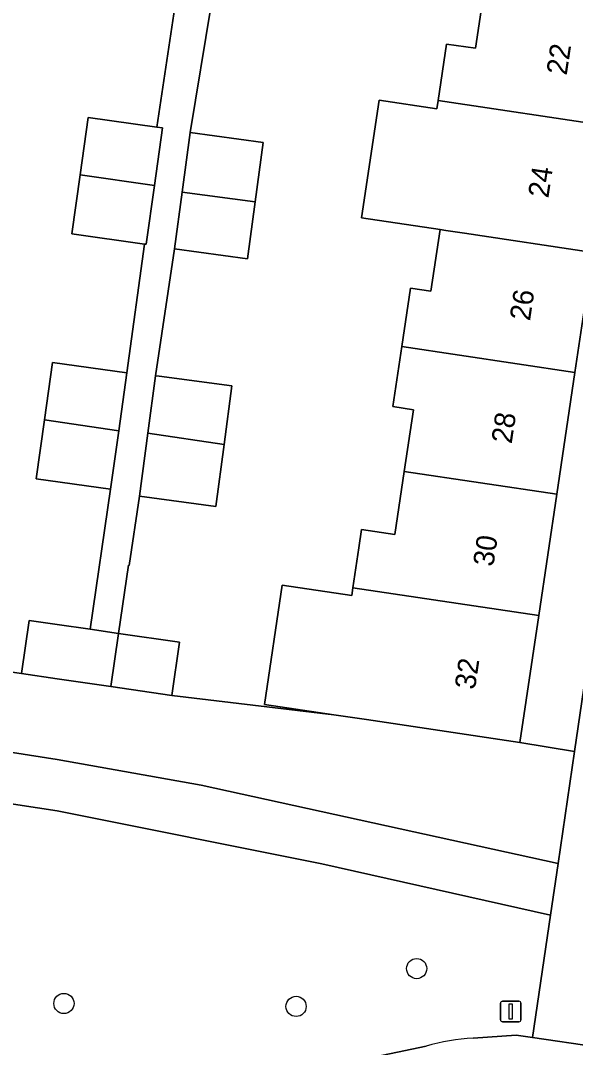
# Model space of a CAD drawing. Extents: x 163683 to 164494, y 382709 to 383872.
# Drawn here: x 163998.22 to 164025.08, y 382929.41 to 382979.16 of the extents above; entities that cross this region are included whole.
import ezdxf

# ---------------------------------------------------------------- set-up
doc = ezdxf.new("R2010")
doc.units = 0
for name, color, linetype in [('IMGEO_Boom', 7, 'Continuous'), ('IMGEO_Erf', 7, 'Continuous'), ('IMGEO_Fietspad_gesloten', 7, 'Continuous'), ('IMGEO_Groenvoorziening', 7, 'Continuous'), ('IMGEO_Pand', 7, 'Continuous'), ('IMGEO_Pand_nummerreeks', 7, 'Continuous'), ('IMGEO_Verkeersbordpaal', 7, 'Continuous'), ('IMGEO_Voetpad_open', 7, 'Continuous')]:
    doc.layers.add(name, color=color, linetype=linetype)

msp = doc.modelspace()

# ---------------------------------------------------------------- linework, layer by layer
at = {"layer": 'IMGEO_Boom'}
for centre in [(164017.398, 382933.229), (164000.323, 382931.542), (164011.562, 382931.398)]:
    msp.add_circle(centre, 0.489, dxfattribs=at)
at = {"layer": 'IMGEO_Erf'}
for points in [[(163988.046, 382949.007), (163998.271, 382947.523), (163998.644, 382950.099), (164000, 382949.902), (164001.595, 382949.67), (164002.581, 382956.45), (163998.98, 382956.95), (163999.378, 382959.814), (163999.763, 382962.588), (164003.364, 382962.087), (164004.231, 382968.332), (164000.709, 382968.821), (164001.107, 382971.685), (164001.492, 382974.459), (164004.816, 382973.997), (164005.734, 382980.133), (164002.361, 382980.571), (164002.742, 382983.508), (163993.289, 382985.074)], [(164007.456, 382979.909), (164006.434, 382973.731), (164009.972, 382973.257), (164009.585, 382970.372), (164009.216, 382967.619), (164005.678, 382968.094), (164004.759, 382961.954), (164004.932, 382961.931), (164008.459, 382961.458), (164008.078, 382958.62), (164007.676, 382955.619), (164003.976, 382956.115), (164003.483, 382952.763), (164003.455, 382952.767), (164002.971, 382949.47), (164005.923, 382949.041), (164005.545, 382946.465), (164013.389, 382945.528), (164010.03, 382946.029), (164010.894, 382951.813), (164014.252, 382951.312), (164014.307, 382951.678), (164014.595, 382953.611), (164014.727, 382954.498), (164016.345, 382954.256), (164016.801, 382957.315), (164017.247, 382960.306), (164016.244, 382960.456), (164016.678, 382963.362), (164017.1, 382966.191), (164018.087, 382966.044), (164018.533, 382969.033), (164014.732, 382969.602), (164015.583, 382975.305), (164018.382, 382974.887), (164018.442, 382975.287), (164018.85, 382978.02), (164020.238, 382977.813), (164020.706, 382980.952)]]:
    msp.add_lwpolyline(points, dxfattribs=at)
msp.add_lwpolyline([(164030.284, 382979.529), (164027.717, 382979.906), (164026.841, 382974.031), (164025.93, 382967.926), (164025.062, 382962.109), (164024.183, 382956.211), (164023.306, 382950.331), (164022.389, 382944.185), (164025.036, 382943.754)], close=True, dxfattribs=at)
at = {"layer": 'IMGEO_Fietspad_gesloten'}
for points in [[(164045.501, 382922.94), (164040.344, 382925.695), (164038.227, 382926.732), (164033.962, 382928.278), (164031.173, 382928.704), (164026.085, 382929.437), (164023.007, 382929.886), (164022.216, 382930.007), (164020.136, 382929.862)], [(164017.857, 382929.469), (164014.694, 382928.806)]]:
    msp.add_lwpolyline(points, dxfattribs=at)
msp.add_arc((164020.577, 382920.499), 9.373, 92.6977, 106.8705, dxfattribs=at)
at = {"layer": 'IMGEO_Groenvoorziening'}
msp.add_lwpolyline([(164025.036, 382943.754), (164022.389, 382944.185), (164014.972, 382945.292), (164013.389, 382945.528), (164005.545, 382946.465), (164002.591, 382946.895), (164000, 382947.272), (163998.271, 382947.523), (163988.046, 382949.007), (163980.685, 382950.079), (163978.336, 382950.439), (163977.619, 382946.126), (163982.561, 382945.602), (163988.036, 382945.238), (164000, 382943.368), (164006.97, 382942.114), (164024.242, 382938.326)], close=True, dxfattribs=at)
for points in [[(164023.876, 382935.821), (164012.814, 382938.309), (164000, 382940.867), (163987.504, 382942.776), (163980.595, 382943.479), (163977.475, 382943.54), (163976.461, 382936.759), (163977.691, 382936.571)], [(164020.136, 382929.862), (164022.216, 382930.007), (164023.007, 382929.886), (164023.876, 382935.821)], [(164014.694, 382928.806), (164017.857, 382929.469)]]:
    msp.add_lwpolyline(points, dxfattribs=at)
msp.add_arc((164020.577, 382920.499), 9.373, 92.6977, 106.8705, dxfattribs=at)
at = {"layer": 'IMGEO_Pand'}
for points in [[(164018.442, 382975.287), (164026.841, 382974.031), (164027.717, 382979.906), (164022.772, 382980.644), (164020.706, 382980.952), (164020.238, 382977.813), (164018.85, 382978.02)], [(164026.841, 382974.031), (164018.442, 382975.287), (164018.382, 382974.887), (164015.583, 382975.305), (164014.732, 382969.602), (164018.533, 382969.033), (164018.805, 382968.992), (164019.714, 382968.856), (164025.93, 382967.926)], [(164005.093, 382973.958), (164004.816, 382973.997), (164001.492, 382974.459), (164001.107, 382971.685), (164004.705, 382971.16)], [(164006.434, 382973.731), (164006.047, 382970.846), (164009.585, 382970.372), (164009.972, 382973.257)], [(164004.705, 382971.16), (164001.107, 382971.685), (164000.709, 382968.821), (164004.231, 382968.332), (164004.31, 382968.321)], [(164009.585, 382970.372), (164006.047, 382970.846), (164005.678, 382968.094), (164009.216, 382967.619)], [(164025.93, 382967.926), (164019.714, 382968.856), (164018.805, 382968.992), (164018.533, 382969.033), (164018.087, 382966.044), (164017.1, 382966.191), (164016.678, 382963.362), (164025.062, 382962.109)], [(164016.801, 382957.315), (164024.183, 382956.211), (164025.062, 382962.109), (164016.678, 382963.362), (164016.244, 382960.456), (164017.247, 382960.306)], [(163999.378, 382959.814), (164002.975, 382959.289), (164003.364, 382962.087), (163999.763, 382962.588)], [(164008.459, 382961.458), (164004.932, 382961.931), (164004.759, 382961.954), (164004.386, 382959.172), (164008.078, 382958.62)], [(163999.378, 382959.814), (163998.98, 382956.95), (164002.581, 382956.45), (164002.975, 382959.289)], [(164008.078, 382958.62), (164004.386, 382959.172), (164003.976, 382956.115), (164007.676, 382955.619)], [(164014.307, 382951.678), (164023.306, 382950.331), (164024.183, 382956.211), (164016.801, 382957.315), (164016.345, 382954.256), (164014.727, 382954.498), (164014.595, 382953.611)], [(164023.306, 382950.331), (164014.307, 382951.678), (164014.252, 382951.312), (164010.894, 382951.813), (164010.03, 382946.029), (164013.389, 382945.528), (164014.972, 382945.292), (164022.389, 382944.185)], [(164002.971, 382949.47), (164001.595, 382949.67), (164000, 382949.902), (163998.644, 382950.099), (163998.271, 382947.523), (164000, 382947.272), (164002.591, 382946.895)], [(164005.923, 382949.041), (164002.971, 382949.47), (164002.591, 382946.895), (164005.545, 382946.465)]]:
    msp.add_lwpolyline(points, close=True, dxfattribs=at)
at = {"layer": 'IMGEO_Verkeersbordpaal'}
for p, q in [((164021.456, 382930.752), (164021.456, 382931.552)), ((164021.456, 382931.552), (164021.456, 382930.752)), ((164021.556, 382931.652), (164022.346, 382931.652)), ((164022.346, 382931.652), (164021.556, 382931.652)), ((164022.446, 382931.552), (164022.446, 382930.752)), ((164022.446, 382930.752), (164022.446, 382931.552)), ((164022.346, 382930.652), (164021.556, 382930.652)), ((164021.556, 382930.652), (164022.346, 382930.652))]:
    msp.add_line(p, q, dxfattribs=at)
msp.add_lwpolyline([(164021.876, 382931.527), (164022.026, 382931.527), (164022.026, 382930.777), (164021.876, 382930.777), (164021.876, 382931.527)], dxfattribs=at)
for centre, start, end in [((164021.556, 382931.552), 90, 180), ((164021.556, 382931.552), 90, 180), ((164022.346, 382931.552), 0, 90), ((164022.346, 382931.552), 360, 90), ((164021.556, 382930.752), 180, 270), ((164021.556, 382930.752), 180, 270), ((164022.346, 382930.752), 270, 0), ((164022.346, 382930.752), 270, 0)]:
    msp.add_arc(centre, 0.1, start, end, dxfattribs=at)
at = {"layer": 'IMGEO_Voetpad_open'}
for points in [[(164042.552, 383044.282), (164040.359, 383044.602), (164040.159, 383043.219), (164039.085, 383035.797), (164039.946, 383035.673), (164039.652, 383033.645), (164038.176, 383023.49), (164037.66, 383019.957), (164036.238, 383020.151), (164035.986, 383018.399), (164033.287, 383000), (164030.709, 382982.425), (164030.284, 382979.529), (164025.036, 382943.754), (164024.242, 382938.326), (164023.876, 382935.821), (164023.007, 382929.886), (164026.085, 382929.437), (164026.287, 382930.934), (164026.311, 382931.123), (164026.328, 382931.232)], [(164005.734, 382980.133), (164004.816, 382973.997), (164005.093, 382973.958), (164004.705, 382971.16), (164004.31, 382968.321), (164004.231, 382968.332), (164003.364, 382962.087), (164002.975, 382959.289), (164002.581, 382956.45), (164001.595, 382949.67), (164002.971, 382949.47), (164003.455, 382952.767), (164003.483, 382952.763), (164003.976, 382956.115), (164004.386, 382959.172), (164004.759, 382961.954), (164005.678, 382968.094), (164006.047, 382970.846), (164006.434, 382973.731), (164007.456, 382979.909)]]:
    msp.add_lwpolyline(points, dxfattribs=at)
msp.add_lwpolyline([(164006.97, 382942.114), (164000, 382943.368), (163988.036, 382945.238), (163982.561, 382945.602), (163977.619, 382946.126), (163977.475, 382943.54), (163980.595, 382943.479), (163987.504, 382942.776), (164000, 382940.867), (164012.814, 382938.309), (164023.876, 382935.821), (164024.242, 382938.326)], close=True, dxfattribs=at)

# ---------------------------------------------------------------- texts
at = {"layer": 'IMGEO_Pand_nummerreeks'}
for s, rotation, p in [('22', 81.5165, (164024.659, 382976.481)), ('24', 81.5147, (164023.771, 382970.531)), ('26', 81.5147, (164022.883, 382964.577)), ('28', 81.5165, (164021.995, 382958.627)), ('30', 81.5165, (164021.107, 382952.673)), ('32', 81.5147, (164020.219, 382946.714))]:
    msp.add_text(s, height=1, rotation=rotation, dxfattribs=at).set_placement(p)

doc.saveas('drawing.dxf')
